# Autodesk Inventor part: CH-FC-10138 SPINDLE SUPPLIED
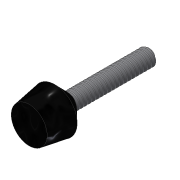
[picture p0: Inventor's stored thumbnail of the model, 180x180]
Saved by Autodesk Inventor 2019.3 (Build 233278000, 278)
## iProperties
Created: 2012-09
Part Number: CH-FC-10138 SPINDLE SUPPLIED
Material: Ogólny
Document SubType Name: Modeling
Designer: CADENGINEERING4
Density: 1 g/cm^3
Appearance: Domyślna
Author: CADENGINEERING4
Revision Number: ÈÎºÎ
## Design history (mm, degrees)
feature "NONE"
node "Bryła1"
